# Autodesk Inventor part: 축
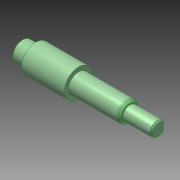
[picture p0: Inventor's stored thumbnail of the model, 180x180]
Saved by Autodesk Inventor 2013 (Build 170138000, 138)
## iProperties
Created: 2023-11
Part Number: 축
Material: 강철, 연강
Document SubType Name: Modeling
Designer: mdu-01
Density: 1 g/cm^3
Author: mdu-01
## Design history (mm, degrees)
sketch "스케치1"
  geometry: L1 (0, 0)-(96, 0); L2 (0, 0)-(0, 6); L3 (1, 7)-(10, 7); L4 (10, 7)-(10, 10); L5 (10, 10)-(40, 10); L6 (40, 10)-(40, 7); L7 (40, 7)-(73.732, 7); L8 (76, 5.711)-(76, 5); L9 (76, 5)-(95, 5); L10 (96, 4)-(96, 0); L11 (0, 6)-(1, 7); L12 (95, 5)-(96, 4); L13 (74.732, 6.732)-(75.75, 6.144); L14 (14, 10)-(14, 7); L15 (14, 7)-(36, 7); L16 (36, 7)-(36, 10); L17 (96, 3.2)-(86, 3.2); L18 (86, 3.2)-(86, 5); A1 r 0.5 centre (75.5, 5.711) between (76, 5.711) and (75.75, 6.144); A2 r 2 centre (73.732, 5) between (74.732, 6.732) and (73.732, 7); 5 further points
  constraints: 36 end point, 10 point on line, 7 parallel, 5 perpendicular, 4 point on circle, 4 tangent, 2 centre point, 2 collinear, 2 horizontal, 2 midpoint, 1 vertical alignment
  dimensions: "d0" = 96 distance of L1.start L1.end; "d1" = 14 diameter of L3 L1; "d2" = 10 distance between parallel lines of L4 L2; "d3" = 30 distance between parallel lines of L6 L4; "d4" = 20 diameter of L5 L1; "d5" = 36 distance between parallel lines of L8 L6; "d6" = 10 diameter of L9 L1; "d7" = 1 distance of L2.end point (0, 7); "d8" = 1 distance of L3.start point (0, 7) (= d7); "d9" = 1 distance of L9.end point (96, 5) (= d7); "d10" = 1 distance of L10.start point (96, 5) (= d9); "d11" = 12 diameter of point (76, 6) L1; "d12" = 30 deg angle of L13 L7; "d13" = 0.5 radius of A1; "d14" = 2 radius of A2; "d15" = 3 distance between parallel lines of L15 L5; "d16" = 22 distance between parallel lines of L16 L14; "d17" = 1.8 distance between parallel lines of L17 L9; "d18" = 10 distance between parallel lines of L18 L10
revolve "회전1" stored, may be unused: angle "d19" = 90 deg
extrude "돌출1" cut sketch "스케치1" stored distance "d20" = 5; taper "d21" = 0 deg
extrude "돌출2" cut sketch "스케치1" stored distance "d22" = 3; taper "d23" = 0 deg
fillet "모깎기1"
fillet "모깎기2"
fillet "모깎기3"
node "솔리드1"
